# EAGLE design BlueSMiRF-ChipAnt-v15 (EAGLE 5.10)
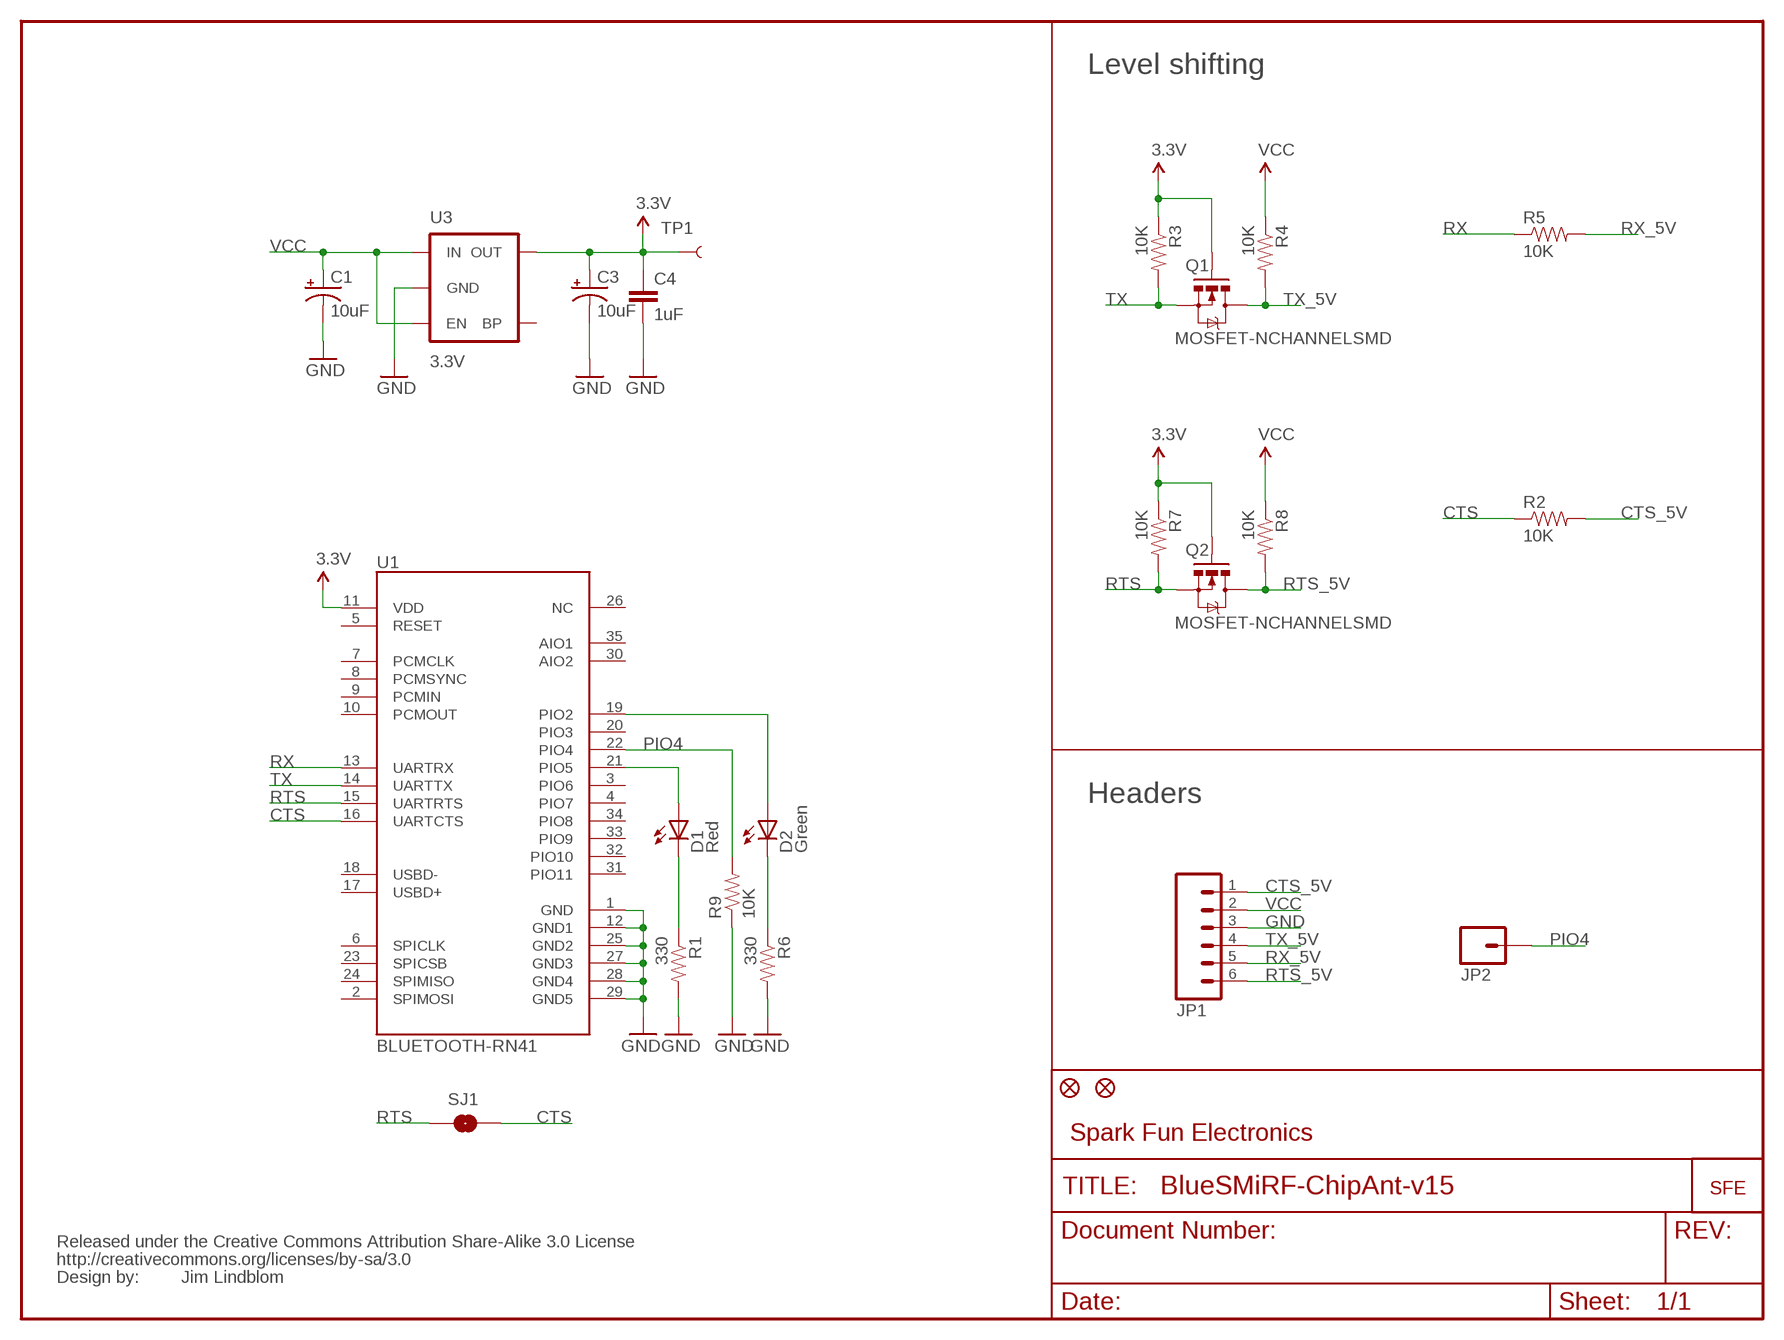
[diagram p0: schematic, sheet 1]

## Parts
C1  10uF  CAP_POL1206  [EIA3216]
C3  10uF  CAP_POL1206  [EIA3216]
C4  1uF  CAP0402-CAP  [0402-CAP]
D1  Red  LED0603  [LED-0603]
D2  Green  LED0603  [LED-0603]
JP1  M06SIP  [1X06]
JP2  M01SMDNS  [1X01NS]
JP3  FIDUCIAL1X2  [FIDUCIAL-1X2]
JP4  FIDUCIAL1X2  [FIDUCIAL-1X2]
Q1  MOSFET-NCHANNELSMD  [SOT23-3]
Q2  MOSFET-NCHANNELSMD  [SOT23-3]
R1  330  RESISTOR0402-RES  [0402-RES]
R2  10K  RESISTOR0402-RES  [0402-RES]
R3  10K  RESISTOR0402-RES  [0402-RES]
R4  10K  RESISTOR0402-RES  [0402-RES]
R5  10K  RESISTOR0402-RES  [0402-RES]
R6  330  RESISTOR0402-RES  [0402-RES]
R7  10K  RESISTOR0402-RES  [0402-RES]
R8  10K  RESISTOR0402-RES  [0402-RES]
R9  10K  RESISTOR0402-RES  [0402-RES]
SJ1  SOLDERJUMPERNO  [SJ_2S-NO]
TP1  TEST-POINT3X5  [PAD.03X.05]
U1  BLUETOOTH-RN41  BLUETOOTH-RN41"  [RN41]
U3  3.3V  V_REG_LDOSMD  [SOT23-5]
U$1  LOGO-SFENEW  [SFE-NEW-WEBLOGO]
U$2  CREATIVE_COMMONS  [CREATIVE_COMMONS]

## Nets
3.3V: C3.A(+) C4.1 Q1.1(G) Q2.1(G) R3.1 R7.1 TP1.P$1 U1.11(VDD) U3.5(OUT)
CTS: R2.1 SJ1.2 U1.16(UARTCTS)
CTS_5V: JP1.1 R2.2
D1: D1.C R1.1
D2: D2.C R6.1
GND: C1.C(-) C3.C(-) C4.2 JP1.3 R1.2 R6.2 R9.1 U1.1(GND) U1.12(GND1) U1.25(GND2) U1.27(GND3) U1.28(GND4) U1.29(GND5) U3.2(GND)
N$1: D1.A U1.21(PIO5)
N$2: D2.A U1.19(PIO2)
PIO4: JP2.1 R9.2 U1.22(PIO4)
RTS: Q2.2(S) R7.2 SJ1.1 U1.15(UARTRTS)
RTS_5V: JP1.6 Q2.3(D) R8.2
RX: R5.1 U1.13(UARTRX)
RX_5V: JP1.5 R5.2
TX: Q1.2(S) R3.2 U1.14(UARTTX)
TX_5V: JP1.4 Q1.3(D) R4.2
VCC: C1.A(+) JP1.2 R4.1 R8.1 U3.1(IN) U3.3(EN)
Unconnected: U1.2(SPIMOSI) U1.3(PIO6) U1.4(PIO7) U1.5(RESET) U1.6(SPICLK) U1.7(PCMCLK) U1.8(PCMSYNC) U1.9(PCMIN) U1.10(PCMOUT) U1.17(USBD+) U1.18(USBD-) U1.20(PIO3) U1.23(SPICSB) U1.24(SPIMISO) U1.26(NC) U1.30(AIO2) U1.31(PIO11) U1.32(PIO10) U1.33(PIO9) U1.34(PIO8) U1.35(AIO1) U3.4(BP)

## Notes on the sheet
- Level shifting
- Headers
- Spark Fun Electronics
- Jim Lindblom

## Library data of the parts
C1 C3 = SparkFun:CAP_POL: Capacitor Polarized
C4 = SparkFun:CAP: Capacitor
D1 D2 = SparkFun:LED: LEDs
JP1 = SparkFun:M06: Header 6 Standard 6-pin 0.1" header. Use with straight break away headers (SKU : PRT-00116), right angle break away headers (PRT-00553), swiss pins (PRT-00743), machine pins (PRT-00117), and female headers (PRT-00115). Molex polarized connector foot print use with SKU : PRT-08094 with associated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
JP2 = SparkFun:M01: Header 1
JP3 JP4 = SparkFun:FIDUCIAL: Fiducial Alignment Points
Q1 Q2 = SparkFun:MOSFET-NCHANNEL
R1-R9 = SparkFun:RESISTOR: Resistor
SJ1 = SparkFun:SOLDERJUMPER: Solder Jumper
TP1 = SparkFun:TEST-POINT
U1 = ScratchPad:BLUETOOTH-RN41
U3 = SparkFun:V_REG_LDO: Voltage Regulator LDO Standard 150mA LDO voltage regulator in SOT-23 layout. Micrel part MIC5205. BP (by-pass) pin is used to lower output noise with 470pF cap.
U$1 = SparkFun:LOGO-SFE: Spark Fun Electronics PCB Logo
U$2 = SparkFun:CREATIVE_COMMONS

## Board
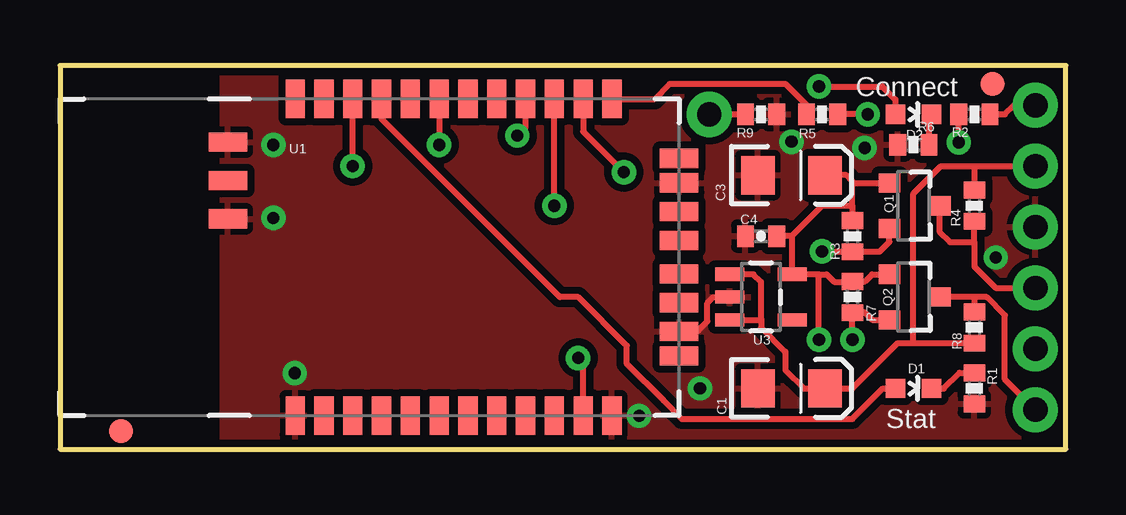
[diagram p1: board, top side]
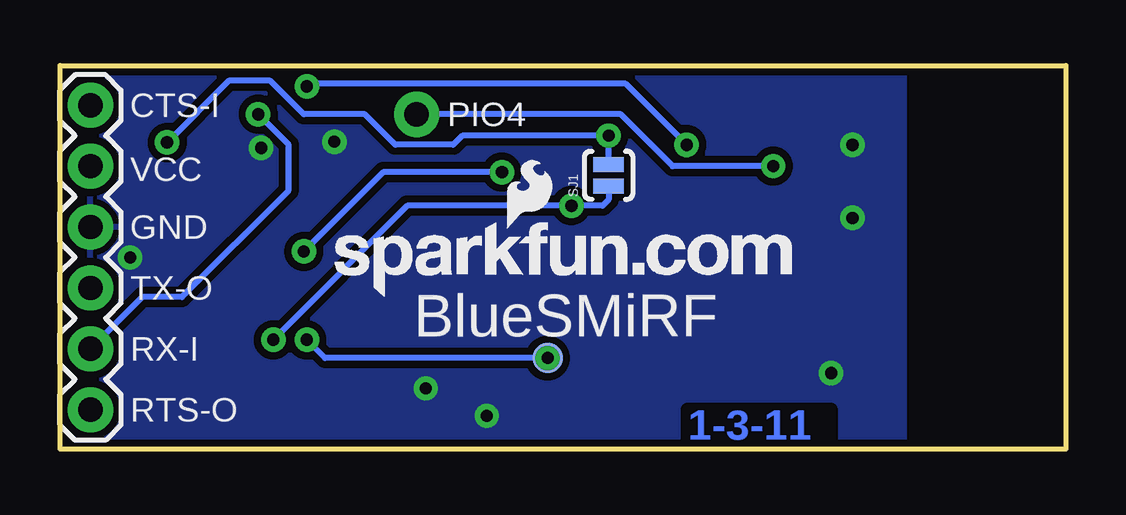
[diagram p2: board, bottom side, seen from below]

Size 41.91 x 16 mm. Coordinates in mm from the lower left corner, seen from the top.
Outline: 0,0 41.91,0 41.91,16 0,16 0,0
Copper layers (1*16): Top 0.035mm / dielectric 1.5mm / Bottom 0.035mm
Design rules "SparkFun *": minimum track width 8mil, minimum drill 20mil, track to track 8mil, track to pad 8mil, pad to pad 8mil, via to via 8mil, smd to smd 8mil, copper to edge 10mil, drill to drill 8mil, minimum pad ring 12mil, minimum via ring 10mil, stop-mask expansion 4mil, vias tented up to drill 20mil, thermal gap 10mil

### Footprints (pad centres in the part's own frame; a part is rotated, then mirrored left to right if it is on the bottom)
EIA3216 = smd 1.4 x 1.6: A 1.4,0; C -1.4,0
0402-CAP = smd 0.7 x 0.9: 1 -0.65,0; 2 0.65,0
LED-0603 = smd 0.8 x 0.8: A 0,-0.75; C 0,0.75
1X06 = drill 1.016 pad 1.88 round: 1 0,0; 2 2.54,0; 3 5.08,0; 4 7.62,0; 5 10.16,0; 6 12.7,0
1X01NS = drill 1.016 pad 1.88 round: 1 0,0
FIDUCIAL-1X2 = smd 1 x 1: 1 0,0
SOT23-3 = smd 0.8 x 0.9: 1 -0.95,-1; 2 0.95,-1; 3 0,1.1
0402-RES = smd 0.7 x 0.9: 1 -0.65,0; 2 0.65,0
SJ_2S-NO = smd 0.635 x 1.27: 1 -0.45,0; 2 0.45,0
PAD.03X.05 = smd 1.27 x 1.27: P$1 0,0
RN41 = smd 0.8 x 1.6: 1 -6.6,-6.6; 2 -5.4,-6.6; 3 -4.2,-6.6; 4 -3,-6.6; 5 -1.8,-6.6; 6 -0.6,-6.6; 7 0.6,-6.6; 8 1.8,-6.6; 9 3,-6.6; 10 4.2,-6.6; 11 5.4,-6.6; 12 6.6,-6.6; 13 6.6,6.6; 14 5.4,6.6; 15 4.2,6.6; 16 3,6.6; 17 1.8,6.6; 18 0.6,6.6; 19 -0.6,6.6; 20 -1.8,6.6; 21 -3,6.6; 22 -4.2,6.6; 23 -5.4,6.6; 24 -6.6,6.6 | smd 1.6 x 0.8: 25 -9.4,4.8; 26 -9.4,3.2; 27 -9.4,1.6; 28 9.4,3.1; 29 9.4,-3.1; 30 9.4,-4.122; 31 9.4,-1.9; 32 9.4,-0.7; 33 9.4,0.7; 34 9.4,1.9; 35 9.4,4.122
SOT23-5 = smd 0.55 x 1.2: 1 -0.95,-1.3; 2 0,-1.3; 3 0.95,-1.3; 4 0.95,1.3; 5 -0.95,1.3

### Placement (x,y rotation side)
C1  30.48,2.54 0 top
C3  30.48,11.43 0 top
C4  29.21,8.89 180 top
D1  35.56,2.54 270 top
D2  35.56,13.97 270 top
JP1  40.64,14.35 270 bottom
JP2  27.05,13.97 0 top
JP3  38.86,15.24 0 top
JP4  2.54,0.76 0 top
Q1  35.56,10.16 270 top
Q2  35.56,6.35 270 top
R1  38.1,2.54 270 top
R2  38.1,13.97 0 top
R3  33.02,8.89 270 top
R4  38.1,10.16 270 top
R5  31.75,13.97 0 top
R6  35.56,12.7 180 top
R7  33.02,6.35 270 top
R8  38.1,5.08 90 top
R9  29.21,13.97 180 top
SJ1  19.05,11.43 90 bottom
TP1  21.59,3.81 0 bottom
U1  16.4,8.01 0 top
U3  29.21,6.35 270 top
U$1  30.48,6.35 0 bottom
U$2  not placed on the board

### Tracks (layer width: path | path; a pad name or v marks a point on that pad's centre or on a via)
3.3V  (via drill 0.51)
  Top 0.254: Q2.1 33.84,7.3 33.54,7 R7.1 33.01,6.99 32.26,6.99 31.94,7.3 31.62,7.3 | 33.02,10.16 R3.1 | 33.02,10.16 33.02,11.18 | 33.02,11.18 32.77,11.43 C3.A | Q1.1 33.09,11.11 33.02,11.18 | 30.48,8.89 C4.1 | 30.48,8.89 30.51,8.86 U3.5 31.62,7.3 | v31.62,4.57 31.62,7.3 | 30.48,8.89 31.75,10.16 33.02,10.16 | U1.11 21.8,3.6 TP1.P$1
  Bottom 0.254: v31.62,4.57 30.86,3.81 TP1.P$1
  other vias: 21.59,3.81
CTS  (via drill 0.51)
  Top 0.254: U1.16 19.4,13.43 v19.05,13.08 | v37.45,12.8 R2.1
  Bottom 0.254: SJ1.2 v19.05,13.08 25.15,13.08 25.53,12.7 27.94,12.7 29.21,13.97 31.75,13.97 33.15,15.37 34.88,15.37 v37.45,12.8
CTS_5V
  Top 0.254: R2.2 39.37,13.97 39.75,14.35 JP1.1
D1
  Top 0.254: R1.1 37.48,3.19 36.83,2.54 D1.C
D2
  Top 0.254: R6.1 36.21,13.87 D2.C
GND  (via drill 0.51)
  Top 0.254: U1.29 25.84,4.95 26.59,4.95 26.98,5.33 26.98,6.1 27.23,6.35 U3.2
  other vias: 30.48,12.83 24.13,1.4 33.53,12.57 8.89,9.65 8.89,12.7 9.78,3.17 38.99,8 26.67,2.54
  pour Bottom (isolate 0.305): 6.73,0 41.91,0 41.91,16 6.73,16
  pour Top (isolate 0.305): 6.73,0 41.91,0 41.91,16 6.73,16
N$1
  Top 0.254: D1.A 34.29,2.54 33.02,1.27 25.91,1.27 25.15,2.03 23.62,3.56 23.62,4.32 21.59,6.35 20.83,6.35 13.4,13.78 U1.21
N$2  (via drill 0.51)
  Top 0.254: v31.62,15.13 34.27,15.13 34.81,14.59 D2.A | U1.19 v15.8,12.7
  Bottom 0.254: v15.8,12.7 18.34,15.24 31.52,15.24 v31.62,15.13
PIO4  (via drill 0.51)
  Top 0.254: JP2.1 R9.2 | v12.19,11.81 U1.22
  Bottom 0.254: JP2.1 18.54,13.97 16.38,11.81 v12.19,11.81
RTS  (via drill 0.51)
  Top 0.254: v20.6,10.16 U1.15 | Q2.2 33.84,5.4 33.53,5.71 33.03,5.71 R7.2 v33.02,4.57
  Bottom 0.254: v33.02,4.57 27.43,10.16 v20.6,10.16 19.3,10.16 19.05,10.41 SJ1.1
RTS_5V
  Top 0.254: 38.1,6.35 Q2.3 | JP1.6 39.37,2.92 39.37,5.59 38.61,6.35 38.1,6.35 | 38.1,6.35 R8.2
RX
  Top 0.254: U1.13 24.77,14.61 25.4,15.24 30.23,15.24 31.1,14.37 R5.1
RX_5V  (via drill 0.51)
  Top 0.254: v33.66,13.97 R5.2
  Bottom 0.254: v33.66,13.97 32.38,12.7 32.38,10.79 36.83,6.35 38.48,6.35 JP1.5
TX  (via drill 0.51)
  Top 0.254: Q1.2 34.56,8.65 34.15,8.24 R3.2 31.77,8.24 v31.75,8.26 | U1.14 21.8,13.25 v23.5,11.56
  Bottom 0.254: v31.75,8.26 29.08,10.92 28.45,11.56 v23.5,11.56
TX_5V
  Top 0.254: JP1.4 38.99,6.73 38.1,7.62 38.1,8.64 | 38.1,8.64 R4.2 | Q1.3 36.66,9.06 37.08,8.64 38.1,8.64
VCC
  Top 0.254: 29.21,5.46 29.21,5.08 30.23,4.06 30.23,3.3 30.99,2.54 C1.A 33.02,2.54 34.91,4.43 35.56,4.43 | U3.1 28.89,7.3 29.21,6.99 29.21,5.46 | U3.3 29.15,5.4 29.21,5.46 | 35.56,4.43 R8.1 | 35.56,4.43 35.56,10.67 36.7,11.81 38.1,11.81 | 38.1,11.81 JP1.2 | 38.1,11.81 R4.1

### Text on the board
Bottom: 1-3-11
tPlace: Connect | Stat
bPlace: CTS-I | PIO4 | VCC | GND | TX-O | BlueSMiRF | RX-I | RTS-O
